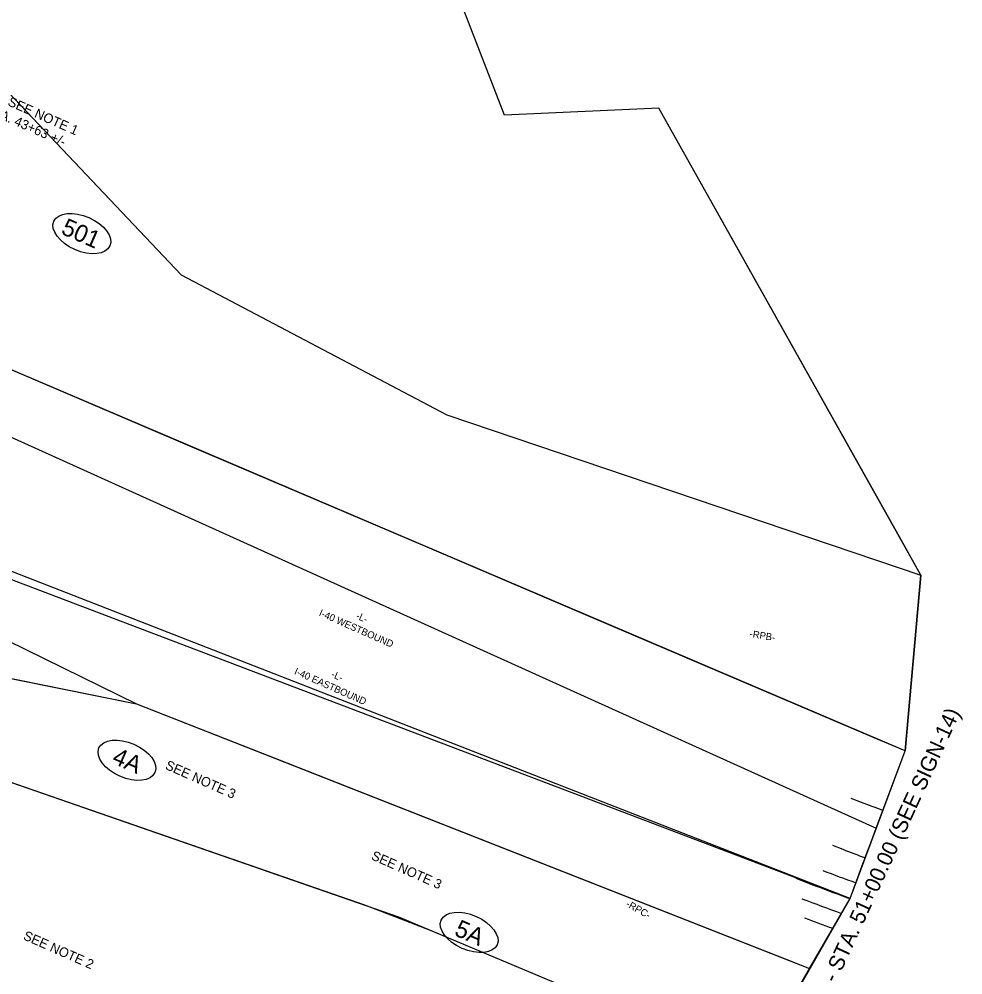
# Model space of a CAD drawing. Extents: x 1639021 to 1641149, y 842052 to 843739.
# Drawn here: x 1639988 to 1640659, y 842458 to 843138 of the extents above; entities that cross this region are included whole.
import ezdxf

# ---------------------------------------------------------------- set-up
doc = ezdxf.new("R2010")
doc.units = 0
for name, color, linetype in [('Default', 7, 'Continuous'), ('Exist Mkg Solid White Edge Line', 7, 'Continuous'), ('Exist Mkg Solid Yellow Edge Line', 7, 'Continuous'), ('Prop Easement Permanent Drainage Utility', 7, 'Continuous'), ('Prop Easement Permanent Utility', 7, 'Continuous'), ('Prop Horizontal Alignment', 7, 'Continuous'), ('Prop Horizontal Alignment Tick Small', 7, 'Continuous'), ('Prop ROW Marker CA CELL', 7, 'Continuous'), ('Prop Sign E Speed Limit XX CELL', 7, 'Continuous'), ('Scratch_Level_2', 7, 'Continuous')]:
    doc.layers.add(name, color=color, linetype=linetype)

msp = doc.modelspace()

# ---------------------------------------------------------------- linework, layer by layer
at = {"layer": 'Exist Mkg Solid White Edge Line'}
msp.add_line((1640579.17, 842584.11), (1640586.51, 842581.26), dxfattribs=at)
for centre, radius, start, end in [((1641269.06, 844342.24), 1888.63, 248.81393, 249.31685), ((1641476.75, 844965.29), 2635.95, 249.33099, 249.79682)]:
    msp.add_arc(centre, radius, start, end, dxfattribs=at)
at = {"layer": 'Exist Mkg Solid Yellow Edge Line'}
msp.add_line((1640566.22, 842550.52), (1640573.5, 842547.7), dxfattribs=at)
for centre, radius, start, end in [((1641269.06, 844342.24), 1924.63, 248.81393, 249.32162), ((1641476.75, 844965.29), 2599.95, 249.33686, 249.88973)]:
    msp.add_arc(centre, radius, start, end, dxfattribs=at)
at = {"layer": 'Prop Easement Permanent Utility'}
for radius, start, end in [(2611.95, 248.98467, 249.88761), (2623.95, 249.18797, 249.84201)]:
    msp.add_arc((1641476.75, 844965.29), radius, start, end, dxfattribs=at)
at = {"layer": 'Prop Horizontal Alignment Tick Small'}
msp.add_lwpolyline([(1639448.15, 842571.05), (1640243.29, 842221.76), (1640272.59, 842288.47), (1640399.95, 842232.52), (1640414.46, 842265.57), (1640431.68, 842258.01), (1640509.88, 842393.53), (1640578.69, 842512.77), (1640588.08, 842537.98), (1640589.14, 842540.82), (1640590.2, 842543.68), (1640594.14, 842554.24), (1640597.32, 842562.78), (1640602.19, 842575.88), (1640617.73, 842617.59), (1640629.05, 842742.44), (1640442.75, 843074.22), (1640333.27, 843069.27), (1640224.04, 843351.63), (1640060.58, 843430.64), (1640037.67, 843446.57), (1639929.48, 843492.21)], dxfattribs=at)
for points in [[(1639772.5, 843143.01), (1639766, 843149.79), (1639764.65, 843151.26), (1639761.37, 843155.14), (1639845.32, 843228.89), (1639847.27, 843226.77), (1639848.62, 843225.3), (1639854.92, 843218.49), (1640103.63, 842955.82), (1640292.21, 842856.39), (1640629.05, 842742.44), (1640617.73, 842617.59), (1639671.17, 843021.26)], [(1639411.76, 843090.84), (1639477.84, 843066.46), (1639639.02, 842996.02), (1640597.32, 842562.78), (1640617.73, 842617.59), (1639671.17, 843021.26), (1639509.99, 843091.7), (1639427.44, 843126.21)], [(1640549.92, 842462.92), (1640578.69, 842512.77), (1639807.4, 842806), (1639556.53, 842931.25), (1639397.02, 843003), (1639376.79, 843011.97), (1639367.96, 842992.05), (1639375.71, 842986.27), (1639535.22, 842914.51), (1640071.73, 842651.02)], [(1640549.92, 842462.92), (1640578.69, 842512.77), (1639813.12, 842811.29), (1639556.53, 842931.25), (1639397.02, 843003), (1639376.79, 843011.97), (1639367.96, 842992.05), (1639375.71, 842986.27), (1639535.22, 842914.51), (1640071.73, 842651.02)], [(1640509.88, 842393.53), (1640258.27, 842499.49), (1639851.27, 842640.65), (1639497.72, 842648.98), (1639258.85, 842745.98), (1639284.06, 842802.84), (1639323.71, 842812.08), (1639324.89, 842810.47), (1639332.61, 842801.05), (1640071.73, 842651.02), (1640549.92, 842462.92)]]:
    msp.add_lwpolyline(points, close=True, dxfattribs=at)
at = {"layer": 'Prop ROW Marker CA CELL'}
msp.add_lwpolyline([(1640432.05, 842257.85), (1640513.21, 842398.08), (1640578.69, 842512.77), (1640598.78, 842566.73), (1640617.73, 842617.59), (1640629.05, 842742.44), (1640614.97, 842767.52), (1640442.75, 843074.22)], dxfattribs=at)
at = {"layer": 'Prop Sign E Speed Limit XX CELL'}
for centre in [(1640033.01, 842985.21), (1640065.02, 842610.93), (1640308.12, 842488.6)]:
    msp.add_ellipse(centre, major_axis=(-19.9, 8.74), ratio=0.571429, dxfattribs=at)
at = {"layer": 'Scratch_Level_2'}
msp.add_lwpolyline([(1639845.32, 843228.89), (1639849.41, 843224.51), (1639833.32, 843207.23), (1639836.58, 843203.56), (1639892.08, 843179.24), (1640103.63, 842955.82), (1640292.21, 842856.39), (1640629.05, 842742.44), (1640617.73, 842617.59), (1640595.71, 842626.98), (1640408.57, 842706.79), (1640278.27, 842762.35), (1640109.67, 842834.25), (1639911.34, 842918.83), (1639760.44, 842983.19), (1639671.17, 843021.26), (1639711.01, 843069.13), (1639777.2, 843151.65), (1639774.61, 843155.19), (1639772.52, 843157.21), (1639766.72, 843160.61)], close=True, dxfattribs=at)
msp.add_lwpolyline([(1639284.06, 842802.84), (1639323.71, 842812.08), (1639324.89, 842810.47), (1639315.52, 842798.54), (1639318.23, 842795.35), (1639494.05, 842768.28), (1639987.22, 842668.18), (1640071.73, 842651.02), (1640171.87, 842611.63), (1640533.86, 842469.24), (1640549.92, 842462.92), (1640509.88, 842393.53), (1640280.71, 842490.04), (1640234.72, 842507.66), (1639851.27, 842640.65), (1639497.72, 842648.98), (1639263.95, 842757.5), (1639284.06, 842802.84)], dxfattribs=at)

# ---------------------------------------------------------------- texts
at = {"layer": 'Default'}
for s, height, p in [('-L- STA. 43+63 +/-', 6.7709, (1639951.22, 843077.26)), ('SEE NOTE 1', 6.771, (1639979.85, 843076.48)), ('SEE NOTE 3', 6.771, (1640091.68, 842604.99)), ('SEE NOTE 3', 6.771, (1640238.01, 842540.71)), ('SEE NOTE 2', 6.771, (1639990.81, 842483.87))]:
    msp.add_text(s, height=height, rotation=336.1242, dxfattribs=at).set_placement(p)
at = {"layer": 'Prop Easement Permanent Drainage Utility'}
msp.add_text('MATCHLINE -L- STA. 51+00.00 (SEE SIGN-14)', height=11, rotation=65.29, dxfattribs=at).set_placement((1640525.9, 842359.34))
at = {"layer": 'Prop Horizontal Alignment'}
for s, rotation, p in [('I-40 WESTBOUND', 336.08714, (1640201, 842713.9)), ('-L- ', 336.08714, (1640227.26, 842711.82)), ('-RPB-', 350.95652, (1640507.1, 842698.5)), ('I-40 EASTBOUND', 336.08714, (1640183.45, 842672.35)), ('-L- ', 336.08714, (1640209.71, 842670.28)), ('-RPC-', 330.60741, (1640419.04, 842507.39))]:
    msp.add_text(s, height=5, rotation=rotation, dxfattribs=at).set_placement(p)
at = {"layer": 'Prop Sign E Speed Limit XX CELL'}
for s, p in [('501', (1640017.55, 842985.29)), ('4A', (1640053.71, 842609.19)), ('5A', (1640296.82, 842486.86))]:
    msp.add_text(s, height=12.271, rotation=336.28496, dxfattribs=at).set_placement(p)

doc.saveas('drawing.dxf')
